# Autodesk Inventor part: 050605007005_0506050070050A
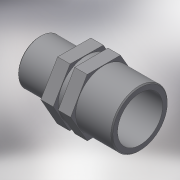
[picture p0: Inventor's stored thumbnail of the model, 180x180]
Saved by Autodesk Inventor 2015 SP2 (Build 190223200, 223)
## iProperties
Created: 2017-05
Part Number: 050605007005_0506050070050A
Material: Generic
Description: PLASSON REDUCING NIPPLE 3/4"-1/2"
Document SubType Name: Modeling
Designer: KIM
Density: 1 g/cm^3
Appearance: Default
Author: KIM
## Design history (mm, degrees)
derived "050605.ipt"
feature "Solid1::050605.ipt"
tag "TaggingFeature1"
body "Solid1"
other parameters: "d0" = 47, "d1" = 26.441, "d5" = 17, "d6" = 4.7, "d8" = 0.47, "d12" = 0, "d14" = 20.955, "d15" = 16.764, "d16" = 21.1528, "d17" = 16, "d18" = 2.35, "d19" = 27, "d21" = 0, "H_" = 47, "R_" = 26.441, "E_" = 27, "l_" = 17, "R_1" = 20.955, "l_1" = 16
